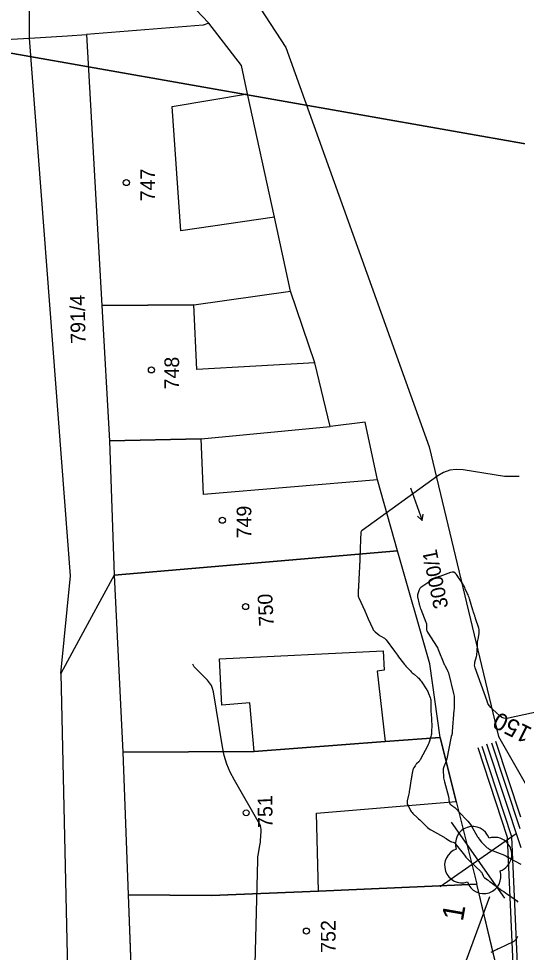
# Model space of a CAD drawing. Extents: x -534481 to -534262, y -1190577 to -1190138.
# Drawn here: x -534439 to -534410.1, y -1190397.5 to -1190343.4 of the extents above; entities that cross this region are included whole.
import ezdxf

# ---------------------------------------------------------------- set-up
doc = ezdxf.new("R2010")
doc.units = 0
for name, color, linetype in [('Bonity', 7, 'Continuous'), ('Definiční body', 7, 'Continuous'), ('Polygon budovy', 7, 'Continuous'), ('Polygon parcely', 7, 'Continuous'), ('Vrstva 18', 7, 'Continuous'), ('Vrstva 19', 7, 'Continuous'), ('Vrstva 30', 7, 'Continuous'), ('Vrstva 31', 7, 'Continuous'), ('Vrstva 35', 7, 'Continuous'), ('Vrstva 46', 7, 'Continuous'), ('Vrstva 48', 7, 'Continuous'), ('Vrstva 54', 7, 'Continuous')]:
    doc.layers.add(name, color=color, linetype=linetype)

msp = doc.modelspace()

# ---------------------------------------------------------------- linework, layer by layer
at = {"layer": 'Bonity'}
msp.add_lwpolyline([(-534409.868, -1190391.439), (-534411.855, -1190385.422)], dxfattribs=at)
at = {"layer": 'Definiční body'}
for p, q in [((-534439.74, -1190344.56), (-534438.35, -1190344.48)), ((-534435.05, -1190344.28), (-534434.16, -1190359.98)), ((-534434.16, -1190359.98), (-534433.73, -1190367.83)), ((-534433.73, -1190367.83), (-534433.45, -1190375.62)), ((-534433.45, -1190375.62), (-534417.02, -1190374.22)), ((-534433.45, -1190375.62), (-534432.95, -1190385.88)), ((-534432.95, -1190385.88), (-534432.64, -1190394.16)), ((-534410.38, -1190402.1), (-534412.44, -1190393.55)), ((-534432.64, -1190394.16), (-534432.33, -1190402.39))]:
    msp.add_line(p, q, dxfattribs=at)
for points in [[(-534425.49, -1190303.95), (-534427.4, -1190310.23), (-534432.23, -1190329.13), (-534431.92, -1190332.1), (-534423.51, -1190345.02), (-534415.2, -1190368.18), (-534411.18, -1190384.97), (-534409.63, -1190387.68)], [(-534438.35, -1190344.48), (-534438.33, -1190339.63), (-534438.5, -1190324.13)], [(-534435.67, -1190327.29), (-534436.59, -1190334.53), (-534427.96, -1190343.61)], [(-534427.96, -1190343.61), (-534428.3, -1190343.74), (-534435.05, -1190344.28)], [(-534423.23, -1190359.15), (-534424.16, -1190354.86), (-534425.72, -1190347.72), (-534426.08, -1190346.07), (-534427.96, -1190343.61)], [(-534438.35, -1190344.48), (-534436.15, -1190344.36), (-534435.05, -1190344.28)], [(-534436.55, -1190381.32), (-534435.98, -1190375.67), (-534438.35, -1190344.48)], [(-534434.16, -1190359.98), (-534428.83, -1190359.95), (-534423.23, -1190359.15)], [(-534420.93, -1190367), (-534421.83, -1190363.31), (-534423.23, -1190359.15)], [(-534417.02, -1190374.22), (-534418.19, -1190370.1), (-534418.9, -1190366.76), (-534420.93, -1190367)], [(-534433.73, -1190367.83), (-534428.4, -1190367.72), (-534420.93, -1190367)], [(-534414.55, -1190385.03), (-534415.16, -1190380.76), (-534417.02, -1190374.22)], [(-534433.45, -1190375.62), (-534434.88, -1190378.25), (-534436.55, -1190381.32)], [(-534436.55, -1190381.32), (-534435.62, -1190422.59), (-534435.57, -1190424.53), (-534435.47, -1190429), (-534438.93, -1190449.34), (-534449.16, -1190465.21), (-534465.46, -1190480.21), (-534468.814, -1190483.101)], [(-534432.95, -1190385.88), (-534425.33, -1190385.85), (-534417.74, -1190385.27), (-534414.55, -1190385.03)], [(-534414.55, -1190385.03), (-534413.63, -1190388.75), (-534412.44, -1190393.55)], [(-534432.64, -1190394.16), (-534427.8, -1190394.2), (-534421.6, -1190393.94), (-534415.89, -1190393.7), (-534412.44, -1190393.55)]]:
    msp.add_lwpolyline(points, dxfattribs=at)
at = {"layer": 'Polygon parcely'}
for points in [[(-534435.05, -1190344.28), (-534434.16, -1190359.98), (-534428.83, -1190359.95), (-534423.23, -1190359.15), (-534424.16, -1190354.86), (-534429.58, -1190355.65), (-534430.09, -1190348.45), (-534425.72, -1190347.72), (-534426.08, -1190346.07), (-534427.96, -1190343.61), (-534428.3, -1190343.74)], [(-534434.16, -1190359.98), (-534433.73, -1190367.83), (-534428.4, -1190367.72), (-534420.93, -1190367), (-534421.83, -1190363.31), (-534428.65, -1190363.7), (-534428.83, -1190359.95)], [(-534433.73, -1190367.83), (-534433.45, -1190375.62), (-534417.02, -1190374.22), (-534418.19, -1190370.1), (-534428.28, -1190370.94), (-534428.4, -1190367.72)], [(-534433.45, -1190375.62), (-534432.95, -1190385.88), (-534425.33, -1190385.85), (-534425.59, -1190383.03), (-534427.22, -1190383.16), (-534427.35, -1190380.48), (-534417.86, -1190380.01), (-534417.8, -1190381.14), (-534418.2, -1190381.2), (-534417.74, -1190385.27), (-534414.55, -1190385.03), (-534415.16, -1190380.76), (-534417.02, -1190374.22)], [(-534432.95, -1190385.88), (-534432.64, -1190394.16), (-534427.8, -1190394.2), (-534421.6, -1190393.94), (-534421.73, -1190389.42), (-534413.63, -1190388.75), (-534414.55, -1190385.03), (-534417.74, -1190385.27), (-534425.33, -1190385.85)], [(-534432.64, -1190394.16), (-534432.33, -1190402.39), (-534427.61, -1190402.33), (-534427.86, -1190398.67), (-534414.87, -1190398.34), (-534413.97, -1190398.32), (-534413.47, -1190402.14), (-534410.38, -1190402.1), (-534412.44, -1190393.55), (-534415.89, -1190393.7), (-534421.6, -1190393.94), (-534427.8, -1190394.2)]]:
    msp.add_lwpolyline(points, close=True, dxfattribs=at)
at = {"layer": 'Vrstva 18'}
for points in [[(-534409.978, -1190369.904), (-534410.683, -1190369.904), (-534410.773, -1190369.904), (-534410.788, -1190369.904), (-534410.803, -1190369.903), (-534410.818, -1190369.902), (-534410.832, -1190369.9), (-534413.227, -1190369.521), (-534413.622, -1190369.495), (-534413.999, -1190369.545), (-534414.358, -1190369.67), (-534414.699, -1190369.872), (-534419.086, -1190373.037), (-534419.116, -1190373.063), (-534419.138, -1190373.094), (-534419.152, -1190373.13), (-534419.157, -1190373.17), (-534419.163, -1190373.337), (-534419.165, -1190373.379), (-534419.166, -1190373.421), (-534419.168, -1190373.463), (-534419.169, -1190373.505), (-534419.194, -1190374.165), (-534419.197, -1190374.233), (-534419.2, -1190374.301), (-534419.202, -1190374.369), (-534419.204, -1190374.437), (-534419.214, -1190374.719), (-534419.217, -1190374.782), (-534419.219, -1190374.844), (-534419.222, -1190374.907), (-534419.225, -1190374.97), (-534419.237, -1190375.22), (-534419.24, -1190375.282), (-534419.243, -1190375.345), (-534419.246, -1190375.407), (-534419.249, -1190375.47), (-534419.292, -1190376.288), (-534419.295, -1190376.344), (-534419.298, -1190376.399), (-534419.3, -1190376.455), (-534419.303, -1190376.511), (-534419.314, -1190376.733), (-534419.313, -1190376.788), (-534419.306, -1190376.842), (-534419.293, -1190376.895), (-534419.273, -1190376.946), (-534418.932, -1190377.702), (-534418.829, -1190377.93), (-534418.726, -1190378.159), (-534418.466, -1190378.735), (-534418.438, -1190378.788), (-534418.405, -1190378.836), (-534418.367, -1190378.879), (-534418.322, -1190378.919), (-534418.106, -1190379.089), (-534418.073, -1190379.114), (-534418.038, -1190379.138), (-534418.002, -1190379.161), (-534417.966, -1190379.182), (-534417.817, -1190379.262), (-534417.782, -1190379.284), (-534417.749, -1190379.31), (-534417.72, -1190379.338), (-534417.693, -1190379.371), (-534417.211, -1190380.025), (-534417.15, -1190380.107), (-534417.088, -1190380.19), (-534417.027, -1190380.272), (-534416.965, -1190380.354), (-534416.683, -1190380.725), (-534416.637, -1190380.784), (-534416.589, -1190380.842), (-534416.54, -1190380.899), (-534416.489, -1190380.954), (-534416.278, -1190381.178), (-534416.229, -1190381.229), (-534416.178, -1190381.279), (-534416.125, -1190381.327), (-534416.071, -1190381.373), (-534415.852, -1190381.555), (-534415.8, -1190381.602), (-534415.751, -1190381.653), (-534415.706, -1190381.707), (-534415.665, -1190381.765), (-534415.338, -1190382.264), (-534415.305, -1190382.318), (-534415.275, -1190382.373), (-534415.248, -1190382.43), (-534415.225, -1190382.489), (-534415.136, -1190382.726), (-534415.117, -1190382.786), (-534415.103, -1190382.847), (-534415.095, -1190382.908), (-534415.093, -1190382.971), (-534415.095, -1190383.33), (-534415.095, -1190383.411), (-534415.093, -1190383.491), (-534415.089, -1190383.572), (-534415.084, -1190383.653), (-534415.059, -1190383.984), (-534415.054, -1190384.066), (-534415.05, -1190384.148), (-534415.048, -1190384.231), (-534415.048, -1190384.313), (-534415.05, -1190384.706), (-534415.053, -1190384.775), (-534415.061, -1190384.843), (-534415.074, -1190384.91), (-534415.092, -1190384.977), (-534415.174, -1190385.241), (-534415.196, -1190385.306), (-534415.22, -1190385.37), (-534415.248, -1190385.434), (-534415.278, -1190385.496), (-534415.706, -1190386.323), (-534415.726, -1190386.357), (-534415.748, -1190386.39), (-534415.773, -1190386.42), (-534415.801, -1190386.449), (-534415.925, -1190386.566), (-534415.949, -1190386.59), (-534415.971, -1190386.616), (-534415.992, -1190386.643), (-534416.011, -1190386.671), (-534416.083, -1190386.787), (-534416.1, -1190386.816), (-534416.113, -1190386.847), (-534416.124, -1190386.878), (-534416.133, -1190386.911), (-534416.191, -1190387.198), (-534416.202, -1190387.257), (-534416.213, -1190387.316), (-534416.224, -1190387.375), (-534416.233, -1190387.435), (-534416.334, -1190388.072), (-534416.347, -1190388.15), (-534416.362, -1190388.228), (-534416.377, -1190388.305), (-534416.394, -1190388.382), (-534416.468, -1190388.708), (-534416.477, -1190388.775), (-534416.475, -1190388.841), (-534416.46, -1190388.906), (-534416.434, -1190388.969), (-534416.304, -1190389.217), (-534416.269, -1190389.277), (-534416.23, -1190389.334), (-534416.186, -1190389.387), (-534416.137, -1190389.436), (-534415.867, -1190389.688), (-534415.805, -1190389.747), (-534415.744, -1190389.805), (-534415.683, -1190389.864), (-534415.622, -1190389.924), (-534415.351, -1190390.192), (-534415.284, -1190390.254), (-534415.213, -1190390.312), (-534415.138, -1190390.364), (-534415.06, -1190390.411), (-534414.37, -1190390.797), (-534414.327, -1190390.821), (-534414.286, -1190390.846), (-534414.244, -1190390.872), (-534414.204, -1190390.899), (-534414.008, -1190391.031), (-534413.984, -1190391.046), (-534413.959, -1190391.058), (-534413.933, -1190391.069), (-534413.906, -1190391.077), (-534413.798, -1190391.106), (-534413.772, -1190391.116), (-534413.748, -1190391.128), (-534413.727, -1190391.145), (-534413.708, -1190391.165), (-534413.154, -1190391.863), (-534413.065, -1190391.97), (-534412.972, -1190392.074), (-534412.876, -1190392.175), (-534412.776, -1190392.272), (-534412.222, -1190392.79), (-534412.195, -1190392.818), (-534412.17, -1190392.849), (-534412.149, -1190392.882), (-534412.131, -1190392.917), (-534412.065, -1190393.061), (-534412.046, -1190393.095), (-534412.024, -1190393.127), (-534411.997, -1190393.155), (-534411.967, -1190393.179), (-534411.815, -1190393.287), (-534411.779, -1190393.313), (-534411.743, -1190393.338), (-534411.707, -1190393.364), (-534411.672, -1190393.39), (-534411.08, -1190393.824), (-534410.976, -1190393.899), (-534410.872, -1190393.973), (-534410.768, -1190394.047), (-534410.663, -1190394.12), (-534410.219, -1190394.427), (-534410.132, -1190394.497), (-534410.06, -1190394.578)], [(-534425.344, -1190400.439), (-534425.133, -1190392.149), (-534425.128, -1190392.053), (-534425.12, -1190391.957), (-534425.108, -1190391.862), (-534425.092, -1190391.767), (-534425.02, -1190391.389), (-534425.003, -1190391.294), (-534424.989, -1190391.199), (-534424.978, -1190391.104), (-534424.969, -1190391.008), (-534424.927, -1190390.481), (-534424.926, -1190390.363), (-534424.942, -1190390.249), (-534424.976, -1190390.139), (-534425.028, -1190390.033), (-534426.484, -1190387.518), (-534426.724, -1190387.056), (-534426.92, -1190386.578), (-534427.072, -1190386.085), (-534427.179, -1190385.575), (-534427.7, -1190382.387), (-534427.745, -1190382.199), (-534427.817, -1190382.025), (-534427.916, -1190381.865), (-534428.042, -1190381.719), (-534428.755, -1190381.007), (-534428.811, -1190380.941), (-534428.856, -1190380.869), (-534428.888, -1190380.792)], [(-534410.075, -1190396.576), (-534410.098, -1190396.615), (-534410.196, -1190396.768), (-534410.222, -1190396.804), (-534410.253, -1190396.835), (-534410.287, -1190396.862), (-534410.326, -1190396.883), (-534411.138, -1190397.27), (-534411.199, -1190397.299), (-534411.26, -1190397.328), (-534411.32, -1190397.358), (-534411.381, -1190397.388), (-534411.622, -1190397.509)]]:
    msp.add_lwpolyline(points, dxfattribs=at)
at = {"layer": 'Vrstva 19'}
msp.add_lwpolyline([(-534407.476, -1190383.24), (-534410.597, -1190383.921), (-534410.735, -1190383.936), (-534410.864, -1190383.918), (-534410.985, -1190383.868), (-534411.097, -1190383.787), (-534411.528, -1190383.394), (-534411.628, -1190383.291), (-534411.714, -1190383.178), (-534411.785, -1190383.056), (-534411.841, -1190382.924), (-534412.526, -1190381.007), (-534412.549, -1190380.926), (-534412.559, -1190380.843), (-534412.556, -1190380.76), (-534412.541, -1190380.677), (-534412.455, -1190380.34), (-534412.437, -1190380.257), (-534412.422, -1190380.173), (-534412.412, -1190380.089), (-534412.407, -1190380.004), (-534412.396, -1190379.656), (-534412.391, -1190379.574), (-534412.384, -1190379.492), (-534412.374, -1190379.411), (-534412.361, -1190379.33), (-534412.303, -1190379.006), (-534412.294, -1190378.926), (-534412.294, -1190378.846), (-534412.305, -1190378.767), (-534412.325, -1190378.688), (-534412.5, -1190378.142), (-534412.514, -1190378.102), (-534412.527, -1190378.061), (-534412.54, -1190378.021), (-534412.554, -1190377.981), (-534412.61, -1190377.819), (-534412.623, -1190377.779), (-534412.637, -1190377.739), (-534412.649, -1190377.698), (-534412.662, -1190377.657), (-534412.861, -1190376.996), (-534412.885, -1190376.921), (-534412.911, -1190376.846), (-534412.94, -1190376.772), (-534412.971, -1190376.699), (-534413.098, -1190376.409), (-534413.132, -1190376.337), (-534413.168, -1190376.267), (-534413.208, -1190376.198), (-534413.25, -1190376.131), (-534413.614, -1190375.583), (-534413.684, -1190375.503), (-534413.765, -1190375.458), (-534413.858, -1190375.447), (-534413.962, -1190375.471), (-534414.569, -1190375.701), (-534414.594, -1190375.71), (-534414.619, -1190375.718), (-534414.645, -1190375.725), (-534414.67, -1190375.73), (-534414.774, -1190375.751), (-534414.799, -1190375.758), (-534414.824, -1190375.767), (-534414.847, -1190375.778), (-534414.87, -1190375.791), (-534415.668, -1190376.333), (-534415.703, -1190376.361), (-534415.732, -1190376.393), (-534415.755, -1190376.429), (-534415.772, -1190376.47), (-534415.85, -1190376.7), (-534415.855, -1190376.714), (-534415.859, -1190376.728), (-534415.862, -1190376.742), (-534415.865, -1190376.757), (-534415.874, -1190376.815), (-534415.875, -1190376.83), (-534415.876, -1190376.844), (-534415.874, -1190376.859), (-534415.872, -1190376.873), (-534415.777, -1190377.298), (-534415.758, -1190377.373), (-534415.737, -1190377.447), (-534415.712, -1190377.52), (-534415.685, -1190377.592), (-534415.378, -1190378.348), (-534415.362, -1190378.395), (-534415.35, -1190378.443), (-534415.343, -1190378.492), (-534415.342, -1190378.542), (-534415.345, -1190378.744), (-534415.342, -1190378.793), (-534415.332, -1190378.84), (-534415.315, -1190378.886), (-534415.291, -1190378.929), (-534414.723, -1190379.792), (-534414.717, -1190379.802), (-534414.712, -1190379.812), (-534414.707, -1190379.823), (-534414.704, -1190379.834), (-534414.691, -1190379.88), (-534414.688, -1190379.891), (-534414.684, -1190379.903), (-534414.68, -1190379.914), (-534414.676, -1190379.925), (-534414.336, -1190380.75), (-534414.316, -1190380.797), (-534414.294, -1190380.843), (-534414.271, -1190380.888), (-534414.247, -1190380.933), (-534414.147, -1190381.11), (-534414.124, -1190381.155), (-534414.103, -1190381.201), (-534414.086, -1190381.248), (-534414.073, -1190381.297), (-534413.782, -1190382.479), (-534413.765, -1190382.558), (-534413.753, -1190382.638), (-534413.746, -1190382.719), (-534413.743, -1190382.8), (-534413.743, -1190383.127), (-534413.744, -1190383.209), (-534413.747, -1190383.29), (-534413.751, -1190383.371), (-534413.757, -1190383.453), (-534413.865, -1190384.689), (-534413.866, -1190384.704), (-534413.867, -1190384.72), (-534413.868, -1190384.735), (-534413.868, -1190384.751), (-534413.868, -1190384.813), (-534413.869, -1190384.829), (-534413.871, -1190384.844), (-534413.874, -1190384.859), (-534413.878, -1190384.874), (-534413.911, -1190384.981), (-534413.918, -1190385.004), (-534413.924, -1190385.027), (-534413.93, -1190385.05), (-534413.934, -1190385.073), (-534414.175, -1190386.267), (-534414.188, -1190386.327), (-534414.205, -1190386.387), (-534414.225, -1190386.445), (-534414.248, -1190386.503), (-534414.345, -1190386.731), (-534414.366, -1190386.788), (-534414.38, -1190386.847), (-534414.386, -1190386.907), (-534414.386, -1190386.968), (-534414.366, -1190387.304), (-534414.359, -1190387.381), (-534414.348, -1190387.456), (-534414.333, -1190387.531), (-534414.314, -1190387.605), (-534414.074, -1190388.46), (-534414.064, -1190388.498), (-534414.056, -1190388.535), (-534414.05, -1190388.574), (-534414.046, -1190388.612), (-534414.029, -1190388.795), (-534414.024, -1190388.819), (-534414.016, -1190388.841), (-534414.004, -1190388.861), (-534413.989, -1190388.879), (-534413.912, -1190388.955), (-534413.897, -1190388.969), (-534413.881, -1190388.982), (-534413.865, -1190388.995), (-534413.848, -1190389.006), (-534413.778, -1190389.051), (-534413.761, -1190389.063), (-534413.745, -1190389.075), (-534413.729, -1190389.089), (-534413.714, -1190389.103), (-534413.042, -1190389.786), (-534412.957, -1190389.879), (-534412.878, -1190389.976), (-534412.805, -1190390.079), (-534412.739, -1190390.186), (-534412.416, -1190390.749), (-534412.387, -1190390.796), (-534412.357, -1190390.842), (-534412.325, -1190390.886), (-534412.291, -1190390.929), (-534412.152, -1190391.099), (-534412.117, -1190391.141), (-534412.08, -1190391.182), (-534412.042, -1190391.221), (-534412.003, -1190391.259), (-534411.828, -1190391.425), (-534411.784, -1190391.462), (-534411.737, -1190391.495), (-534411.687, -1190391.524), (-534411.634, -1190391.547), (-534410.832, -1190391.861), (-534410.806, -1190391.872), (-534410.781, -1190391.883), (-534410.756, -1190391.896), (-534410.732, -1190391.91), (-534410.638, -1190391.968), (-534410.614, -1190391.983), (-534410.59, -1190391.997), (-534410.566, -1190392.01), (-534410.541, -1190392.024), (-534409.888, -1190392.376)], dxfattribs=at)
at = {"layer": 'Vrstva 30'}
for points in [[(-534279.901, -1190266.866), (-534426.145, -1190241.079), (-534444.378, -1190344.484), (-534298.134, -1190370.27)], [(-534298.134, -1190370.27), (-534444.378, -1190344.484), (-534462.611, -1190447.888), (-534316.367, -1190473.675)]]:
    msp.add_lwpolyline(points, dxfattribs=at)
at = {"layer": 'Vrstva 31'}
msp.add_lwpolyline([(-534405.695, -1190512.351), (-534434.703, -1190456.89), (-534411.68, -1190394.248)], dxfattribs=at)
at = {"layer": 'Vrstva 35'}
for points in [[(-534410.645, -1190390.84), (-534412.361, -1190385.645)], [(-534410.397, -1190390.795), (-534412.125, -1190385.56)], [(-534409.916, -1190390.337), (-534411.561, -1190385.357)], [(-534409.879, -1190389.652), (-534411.326, -1190385.272)], [(-534405.407, -1190514.348), (-534394.258, -1190501.982), (-534392.12, -1190496.869), (-534393.492, -1190488.211), (-534397.35, -1190478.035), (-534403.219, -1190464.54), (-534405.491, -1190456.905), (-534409.051, -1190433.21), (-534409.998, -1190427.948), (-534410.066, -1190416.042), (-534409.827, -1190409.421), (-534410.645, -1190390.84)], [(-534405.057, -1190514.333), (-534394.044, -1190502.118), (-534391.862, -1190496.9), (-534393.249, -1190488.146), (-534397.118, -1190477.94), (-534402.983, -1190464.455), (-534405.247, -1190456.85), (-534408.804, -1190433.17), (-534409.748, -1190427.925), (-534409.816, -1190416.046), (-534409.577, -1190409.42), (-534410.397, -1190390.795)]]:
    msp.add_lwpolyline(points, dxfattribs=at)
at = {"layer": 'Vrstva 46'}
for centre in [(-534432.746, -1190352.861), (-534431.293, -1190363.724), (-534427.182, -1190372.443), (-534425.833, -1190377.446), (-534425.8, -1190389.404), (-534422.307, -1190396.261)]:
    msp.add_circle(centre, 0.175, dxfattribs=at)
at = {"layer": 'Vrstva 48'}
for p, q in [((-534416.284, -1190370.57), (-534415.597, -1190372.459)), ((-534415.597, -1190372.459), (-534415.867, -1190372.208)), ((-534415.597, -1190372.459), (-534415.551, -1190372.093))]:
    msp.add_line(p, q, dxfattribs=at)
at = {"layer": 'Vrstva 54'}
for p, q in [((-534410.812, -1190394.345), (-534413.896, -1190389.941)), ((-534414.556, -1190393.685), (-534410.152, -1190390.601))]:
    msp.add_line(p, q, dxfattribs=at)
msp.add_circle((-534412.354, -1190392.143), 0.001, dxfattribs=at)
for centre, start, end in [((-534412.673, -1190391.195), 18.6209, 198.6209), ((-534411.406, -1190391.824), 288.6209, 108.6209), ((-534413.301, -1190392.462), 108.6209, 288.6209), ((-534412.034, -1190393.09), 198.6209, 18.6209)]:
    msp.add_arc(centre, 1, start, end, dxfattribs=at)

# ---------------------------------------------------------------- texts
at = {"layer": 'Polygon budovy'}
for s, rotation, p in [('747', 90, (-534431.08, -1190353.948)), ('791/4', 91, (-534435.107, -1190362.204)), ('748', 90, (-534429.687, -1190364.859)), ('749', 90, (-534425.5, -1190373.493)), ('3000/1', 101.5337, (-534414.077, -1190377.479)), ('750', 93, (-534424.196, -1190378.574)), ('751', 91, (-534424.261, -1190390.273)), ('752', 90, (-534420.619, -1190397.524))]:
    msp.add_text(s, height=0.85, rotation=rotation, dxfattribs=at).set_placement(p)
at = {"layer": 'Vrstva 31'}
for s, height, rotation, p in [('150', 1, 153.4033, (-534409.166, -1190384.52)), ('1', 1.25, 80, (-534413.243, -1190395.733))]:
    msp.add_text(s, height=height, rotation=rotation, dxfattribs=at).set_placement(p)

doc.saveas('drawing.dxf')
